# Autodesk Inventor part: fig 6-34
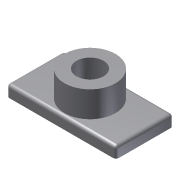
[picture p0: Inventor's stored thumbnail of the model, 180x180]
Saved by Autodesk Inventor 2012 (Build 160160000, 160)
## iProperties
Created: 2004-05
Part Number: fig 6-34
Document SubType Name: Modeling
Designer: CADCIM Technologies
Manufacturer: Standard
Standards Organization: Custom
Density: 1 g/cm^3
Material: Default
Author: CADCIM Technologies
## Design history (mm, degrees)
sketch "Sketch1"
  geometry: L1 (-39.276, -18.692)-(33.721, -18.692); L2 (33.721, -18.692)-(33.721, 19.728); L3 (33.721, 19.728)-(-39.276, 19.728); L4 (-39.276, 19.728)-(-39.276, -18.692)
  constraints: 8 end point, 2 parallel, 1 horizontal, 1 perpendicular
extrude "Extrusion1" new body sketch "Sketch1" distance "d0" = 7.5; taper "d1" = 0 deg
sketch "Sketch2"
  geometry: C1 r 17 at (-2.778, 0.518)
  constraints: 1 centre point
  dimensions: "d16" = 34 diameter of C1
extrude "Extrusion2" join sketch "Sketch2" distance "d3" = 17.25; taper "d4" = 0 deg
hole "Hole1" diameter "d8" = 18; stored, may be unused: countersink angle "d12" = 90 deg, drill point angle "d14" = 118 deg; dims "d6" = 10, "d7" = 10, "d9" = 6, "d10" = 4, "d11" = 2, "d13" = 8
fillet "Fillet4" dims "d17" = 2
body "Solid1"
